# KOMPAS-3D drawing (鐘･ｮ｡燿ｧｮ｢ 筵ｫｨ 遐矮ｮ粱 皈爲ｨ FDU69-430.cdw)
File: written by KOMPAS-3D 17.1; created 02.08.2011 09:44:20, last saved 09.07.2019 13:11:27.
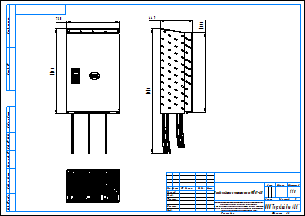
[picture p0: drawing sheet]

Title block, sheet 1: name: Преобразователи частоты серии FDU69-430; scale: 1:10; sheets: 1; sheet format: A3; stored path: \\adlc.lan\data\АДЛ_ПКД\3D-модели\Поставщики\Оборудование Emotron\Преобразователи частоты\Серия FDU 2.0\KOMPAS 2D\Преобразователи частоты серии FDU69-430.cdw

Views: Спереди 1
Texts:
  Рама для чертежей
  Лит-Масса-Масштаб
  Материал-Предприятие
  Масштаб
  Изм.
  Лист
  № докум.
  Подп.
  Дата
  Лит.
  Разраб.
  Пров.
  Т.контр.
  Листов
  Внимание! Данный продукт является объектом авторского права ООО «Торговый Дом АДЛ».
  Запрещается изменение, копирование, распространение
  (в том числе путем копирования на другие сайты и ресурсы в Интернете)
  или любое иное использование информации и объектов без предварительного
  согласия правообладателя (ООО «Торговый Дом АДЛ»).
  Н.контр.
  Утв.
  ООО "Торговый дом АДЛ"
  Изменение
  Номер документа
  Подпись
  Обозначение документа
  Наименование изделия
  Масса изделия по ГОСТ 2.109-73
  Порядковый номер листа
  Общее количество листов в документе
  Характер работы, выполненной лицом, подписавшим документ
  Наименование или индекс предприятия, выпускающего документ
  Инв. № подл.
  Подп. и дата
  Взам. инв. №
  Инв. № дубл.
  Инвентарный номер подлинника по ГОСТ 2.501-68
  Подпись принявшего подлинник в отдел технической документации
  Инвентарный номер подлинника, взамен которого выпущен данный подлинник
  Инвентарный номер дубликата по ГОСТ 2.502-68
  Подпись принявшего дубликат в отдел технической документации
  Справ. №
  Перв. примен.
  Обозначение документа, взамен или на основании которого выпущен данный документ
  Обозначение документа, в котором впервые записан данный документ
  Подпись лица, копировавшего чертеж
  Обозначение формата листа
  !Рама для чертежа
Dimensions and other numbers on the sheet: 1176; 730; 449; 1096; 1718; 1:10; 1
